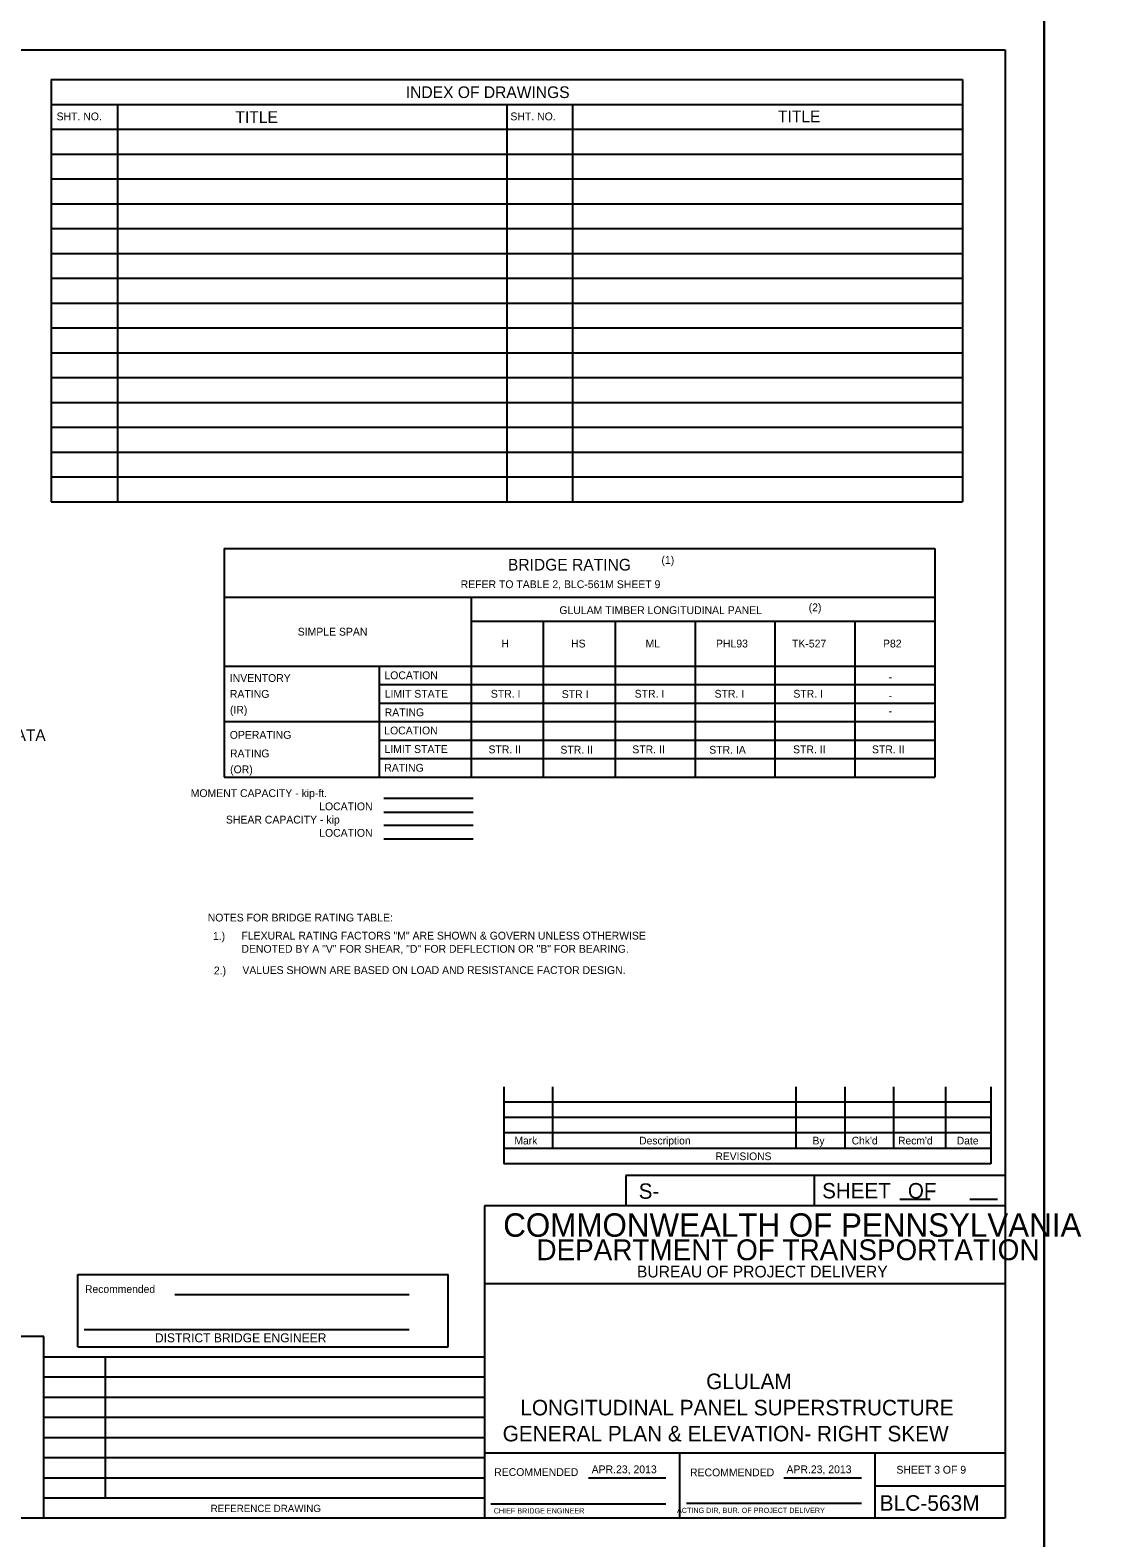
# Model space of a CAD drawing. Extents: x 638268 to 640277, y 295465 to 298435.
# Drawn here: x 638887 to 639304, y 296661 to 297240 of the extents above; entities that cross this region are included whole.
import ezdxf

# ---------------------------------------------------------------- set-up
doc = ezdxf.new("R2010")
doc.units = 0
for name, color, linetype in [('1', 7, 'Continuous'), ('2', 7, 'Continuous'), ('4', 7, 'Continuous'), ('7', 7, 'Continuous'), ('PLT-BNDY', 7, 'Continuous')]:
    doc.layers.add(name, color=color, linetype=linetype)

msp = doc.modelspace()

# ---------------------------------------------------------------- linework, layer by layer
at = {"layer": '2'}
for p, q in [((638475.46, 297232.46), (639261.46, 297232.46)), ((639261.46, 297232.46), (639261.46, 296668.46)), ((639068.92, 296834.15), (639068.92, 296804.62)), ((639087.62, 296834.15), (639087.62, 296810.53)), ((639181.13, 296834.15), (639181.13, 296810.53)), ((639199.83, 296834.15), (639199.83, 296810.53)), ((639218.53, 296834.15), (639218.53, 296810.53)), ((639238.59, 296834.15), (639238.59, 296810.53)), ((639255.94, 296834.15), (639255.94, 296804.62)), ((639255.94, 296828.24), (639068.92, 296828.24)), ((639255.94, 296822.34), (639068.92, 296822.34)), ((639255.94, 296816.43), (639068.92, 296816.43)), ((639255.94, 296810.53), (639068.92, 296810.53)), ((639255.94, 296804.62), (639068.92, 296804.62)), ((639261.46, 296800.11), (639115.78, 296800.11)), ((639115.78, 296800.11), (639115.78, 296788.46)), ((639188.09, 296800.11), (639188.09, 296788.46)), ((639261.46, 296800.11), (639261.46, 296788.46)), ((639220.95, 296791), (639232.6, 296791)), ((639247.83, 296791), (639258.56, 296791)), ((639261.46, 296788.46), (639061.46, 296788.46)), ((639061.46, 296788.46), (639061.46, 296668.46)), ((639261.46, 296788.46), (639115.78, 296788.46)), ((638905.4, 296734.31), (638905.4, 296762.1)), ((638905.4, 296762.1), (639047.58, 296762.1)), ((638905.4, 296734.31), (638905.4, 296762.1)), ((638905.4, 296762.1), (639047.58, 296762.1)), ((638905.4, 296734.31), (638905.4, 296762.1)), ((638905.4, 296762.1), (639047.58, 296762.1)), ((639047.58, 296734.31), (639047.58, 296762.1)), ((639047.58, 296734.31), (639047.58, 296762.1)), ((639047.58, 296734.31), (639047.58, 296762.1)), ((639261.46, 296758.46), (639061.46, 296758.46)), ((638942.6, 296754.38), (639032.62, 296754.38)), ((638942.6, 296754.38), (639032.62, 296754.38)), ((638942.6, 296754.38), (639032.62, 296754.38)), ((638907.84, 296741.02), (639032.62, 296741.02)), ((638907.84, 296741.02), (639032.62, 296741.02)), ((638907.84, 296741.02), (639032.62, 296741.02)), ((638905.4, 296734.31), (639047.58, 296734.31)), ((638905.4, 296734.31), (639047.58, 296734.31)), ((638905.4, 296734.31), (639047.58, 296734.31)), ((639261.46, 296693.46), (639061.46, 296693.46)), ((639136.46, 296668.46), (639136.46, 296693.46)), ((639211.46, 296693.46), (639211.46, 296668.46)), ((639101.42, 296683.96), (639131.19, 296683.96)), ((639176.42, 296683.96), (639206.33, 296683.96)), ((639211.46, 296680.96), (639261.46, 296680.96)), ((639063.96, 296673.96), (639131.19, 296673.96)), ((639139.08, 296674.33), (639206.33, 296674.33)), ((639261.46, 296668.46), (638475.46, 296668.46))]:
    msp.add_line(p, q, dxfattribs=at)
at = {"layer": '4'}
for p, q in [((638895.09, 297220.95), (639245.09, 297220.95)), ((638895.09, 297220.95), (638895.09, 297058.84)), ((639245.09, 297220.95), (639245.09, 297058.84)), ((638895.09, 297211.41), (639070.09, 297211.41)), ((638920.56, 297211.41), (638920.56, 297058.84)), ((639070.09, 297211.41), (639245.09, 297211.41)), ((639070.09, 297211.41), (639070.09, 297058.84)), ((639095.26, 297211.41), (639095.26, 297058.84)), ((638895.09, 297201.87), (639070.09, 297201.87)), ((639070.09, 297201.87), (639245.09, 297201.87)), ((638895.09, 297192.34), (639070.09, 297192.34)), ((639070.09, 297192.34), (639245.09, 297192.34)), ((638895.09, 297182.8), (639070.09, 297182.8)), ((639070.09, 297182.8), (639245.09, 297182.8)), ((638895.09, 297173.27), (639070.09, 297173.27)), ((639070.09, 297173.27), (639245.09, 297173.27)), ((638895.09, 297163.73), (639070.09, 297163.73)), ((639070.09, 297163.73), (639245.09, 297163.73)), ((638895.09, 297154.2), (639070.09, 297154.2)), ((639070.09, 297154.2), (639245.09, 297154.2)), ((638895.09, 297144.66), (639070.09, 297144.66)), ((639070.09, 297144.66), (639245.09, 297144.66)), ((638895.09, 297135.12), (639070.09, 297135.12)), ((639070.09, 297135.12), (639245.09, 297135.12)), ((638895.09, 297125.59), (639070.09, 297125.59)), ((639070.09, 297125.59), (639245.09, 297125.59)), ((638895.09, 297116.05), (639070.09, 297116.05)), ((639070.09, 297116.05), (639245.09, 297116.05)), ((638895.09, 297106.52), (639070.09, 297106.52)), ((639070.09, 297106.52), (639245.09, 297106.52)), ((638895.09, 297096.98), (639070.09, 297096.98)), ((639070.09, 297096.98), (639245.09, 297096.98)), ((638895.09, 297087.45), (639070.09, 297087.45)), ((639070.09, 297087.45), (639245.09, 297087.45)), ((638895.09, 297077.91), (639070.09, 297077.91)), ((639070.09, 297077.91), (639245.09, 297077.91)), ((638895.09, 297068.37), (639070.09, 297068.37)), ((639070.09, 297068.37), (639245.09, 297068.37)), ((638895.09, 297058.84), (639245.09, 297058.84)), ((639021.08, 296988.66), (639234.39, 296988.66)), ((639021.08, 296981.54), (639234.39, 296981.54)), ((639021.08, 296967.31), (639234.39, 296967.31)), ((639021.08, 296960.19), (639234.39, 296960.19)), ((639022.87, 296944.98), (639057.14, 296944.98)), ((639022.87, 296939.65), (639057.14, 296939.65)), ((639022.87, 296934.61), (639057.14, 296934.61)), ((639022.87, 296929.43), (639057.14, 296929.43)), ((638892.25, 296738.31), (638754.05, 296738.31)), ((638892.25, 296668.46), (638892.25, 296738.31)), ((639061.46, 296730.34), (638892.25, 296730.34)), ((638915.96, 296676.19), (638915.96, 296730.34)), ((639061.46, 296722.6), (638892.25, 296722.6)), ((639061.46, 296714.87), (638892.25, 296714.87)), ((639061.46, 296707.13), (638892.25, 296707.13)), ((639061.46, 296699.4), (638892.25, 296699.4)), ((639061.46, 296691.66), (638892.25, 296691.66)), ((639061.46, 296683.93), (638892.25, 296683.93)), ((639061.46, 296676.19), (638892.25, 296676.19))]:
    msp.add_line(p, q, dxfattribs=at)
at = {"layer": '7'}
for p, q in [((638961.6, 297040.85), (638961.6, 296953.08)), ((638961.6, 297040.85), (639234.39, 297040.85)), ((639234.39, 297040.85), (639234.39, 296953.08)), ((638961.6, 297022.16), (639234.39, 297022.16)), ((639056.44, 297022.16), (639056.44, 296953.08)), ((639056.44, 297012.95), (639234.39, 297012.95)), ((639084.06, 297012.95), (639084.06, 296953.08)), ((639111.67, 297012.95), (639111.67, 296953.08)), ((639142.35, 297012.95), (639142.35, 296953.08)), ((639173.03, 297012.95), (639173.03, 296953.08)), ((639203.71, 297012.95), (639203.71, 296953.08)), ((638961.6, 296995.77), (639234.39, 296995.77)), ((639021.08, 296995.77), (639021.08, 296953.08)), ((638961.6, 296974.42), (639234.39, 296974.42)), ((638961.6, 296953.08), (639234.39, 296953.08))]:
    msp.add_line(p, q, dxfattribs=at)
at = {"layer": 'PLT-BNDY'}
for points in [[(638435.46, 297247.46), (639276.46, 297247.46), (639276.46, 296653.46), (638435.46, 296653.46)], [(639276.46, 297247.46), (640117.46, 297247.46), (640117.46, 296653.46), (639276.46, 296653.46)]]:
    msp.add_lwpolyline(points, close=True, dxfattribs=at)

# ---------------------------------------------------------------- texts
at = {"layer": '1'}
msp.add_text('SHEET 3 OF 9', height=3, dxfattribs=at).set_placement((639219.7, 296685.62))
at = {"layer": '2'}
for s, height, p in [('MOMENT CAPACITY - kip-ft.', 3, (638948.69, 296945.44)), ('LOCATION', 3, (638998.03, 296940.36)), ('SHEAR CAPACITY - kip', 3, (638962.22, 296935.27)), ('LOCATION', 3, (638998.03, 296930.19)), ('Mark', 2.952, (639073.02, 296812.03)), ('Description', 2.9523, (639120.92, 296812.03)), ('By', 2.952, (639187.49, 296812.03)), ("Chk'd", 2.952, (639202.52, 296812.03)), ("Recm'd", 2.953, (639220.33, 296812.03)), ('Date', 2.952, (639242.86, 296812.03)), ('REVISIONS', 2.952, (639150.2, 296806.01)), ('S-', 5.905, (639120.73, 296791.17)), ('COMMONWEALTH OF PENNSYLVANIA', 9, (639068.71, 296776.58)), ('DEPARTMENT OF TRANSPORTATION', 8.0002, (639081.46, 296767.58)), ('BUREAU OF PROJECT DELIVERY', 4.5, (639120.05, 296760.96)), ('Recommended', 2.9682, (638908.11, 296755)), ('Recommended', 2.9682, (638908.11, 296755)), ('Recommended', 2.9682, (638908.11, 296755)), ('GENERAL PLAN & ELEVATION- RIGHT SKEW', 5.9714, (639068.49, 296698)), ('APR.23, 2013', 3, (639102.67, 296685.77)), ('APR.23, 2013', 3, (639177.48, 296685.77)), ('BLC-563M', 6, (639213.27, 296671.33)), ('CHIEF BRIDGE ENGINEER', 2.0002, (639065.05, 296670.33)), ('  ACTING DIR, BUR. OF PROJECT DELIVERY', 2.0002, (639133.9, 296670.51))]:
    msp.add_text(s, height=height, dxfattribs=at).set_placement(p)
for s, height, rotation, p in [('SHEET   OF', 5.907, 360, (639191.18, 296791.31)), ('DISTRICT BRIDGE ENGINEER', 3.4629, 359.99999, (638934.95, 296736.04)), ('DISTRICT BRIDGE ENGINEER', 3.4629, 359.99999, (638934.95, 296736.04)), ('DISTRICT BRIDGE ENGINEER', 3.4629, 359.99999, (638934.95, 296736.04)), ('RECOMMENDED', 3, 360, (639065.23, 296684.71)), ('RECOMMENDED', 3, 360, (639140.44, 296684.58))]:
    msp.add_text(s, height=height, rotation=rotation, dxfattribs=at).set_placement(p)
at = {"layer": '4'}
for s, height, p in [('INDEX OF DRAWINGS', 4.4792, (639031.3, 297213.89)), ('SHT. NO.', 3, (638897.2, 297205.33)), ('TITLE', 4.479, (638965.87, 297204.35)), ('SHT. NO.', 3, (639071.46, 297205.33)), ('TITLE', 4.479, (639174.21, 297204.61)), ('BRIDGE RATING', 4.4792, (639070.51, 297032.44)), ('(1)', 3, (639129.46, 297034.99)), ('REFER TO TABLE 2, BLC-561M SHEET 9', 3, (639052.36, 297025.67)), ('GLULAM TIMBER LONGITUDINAL PANEL', 3, (639090.27, 297015.72)), ('(2)', 3, (639186, 297016.79)), ('SIMPLE SPAN', 3, (638989.8, 297007.45)), ('H', 3, (639068, 297002.89)), ('HS', 3, (639094.77, 297002.89)), ('ML', 3, (639123.36, 297002.89)), ('PHL93', 3, (639150.41, 297002.89)), ('TK-527', 3, (639179.6, 297002.89)), ('P82', 3, (639214.54, 297002.89)), ('INVENTORY', 3, (638963.7, 296989.66)), ('LOCATION', 3, (639023.09, 296990.71)), ('RATING', 3, (638963.74, 296983.56)), ('LIMIT STATE', 3, (639023.2, 296983.6)), ('STR. I', 3, (639063.95, 296983.6)), ('STR I', 3, (639091.19, 296983.47)), ('STR. I', 3, (639119.18, 296983.61)), ('STR. I', 3, (639149.86, 296983.61)), ('STR. I', 3, (639180.13, 296983.61)), ('-', 3, (639216.72, 296990.07)), ('-', 3, (639216.72, 296982.96)), ('(IR)', 3, (638963.78, 296977.45)), ('RATING', 3, (639023.18, 296976.48)), ('-', 3, (639216.72, 296977.05)), ('HYDRAULIC DATA', 4.4292, (638841.31, 296967.02)), ('OPERATING', 3, (638963.71, 296967.82)), ('LOCATION', 3, (639023.02, 296969.5)), ('RATING', 3, (638963.79, 296960.68)), ('LIMIT STATE', 3, (639023.1, 296962.38)), ('STR. II', 3, (639063.04, 296962.25)), ('STR. II', 3, (639090.66, 296962.13)), ('STR. II', 3, (639118.27, 296962.26)), ('STR. IA', 3, (639147.82, 296962.1)), ('STR. II', 3, (639180, 296962.26)), ('STR. II', 3, (639210.31, 296962.26)), ('(OR)', 3, (638963.83, 296954.58)), ('RATING', 3, (639023.02, 296955.18)), ('NOTES FOR BRIDGE RATING TABLE:', 3, (638955.22, 296897.66)), ('1.)', 3, (638957.23, 296890.58)), ('FLEXURAL RATING FACTORS "M" ARE SHOWN & GOVERN UNLESS OTHERWISE', 3, (638968.18, 296890.72)), ('DENOTED BY A "V" FOR SHEAR, "D" FOR DEFLECTION OR "B" FOR BEARING.', 3, (638968.18, 296885.65)), ('2.)', 3, (638957.59, 296877.34)), ('VALUES SHOWN ARE BASED ON LOAD AND RESISTANCE FACTOR DESIGN.', 3, (638968.54, 296877.48)), ('GLULAM', 5.971, (639146.64, 296718.06)), ('LONGITUDINAL PANEL SUPERSTRUCTURE', 5.9714, (639075.27, 296707.99))]:
    msp.add_text(s, height=height, dxfattribs=at).set_placement(p)
msp.add_text('REFERENCE DRAWING', height=2.8082, rotation=360, dxfattribs=at).set_placement((638956.34, 296670.86))

doc.saveas('drawing.dxf')
